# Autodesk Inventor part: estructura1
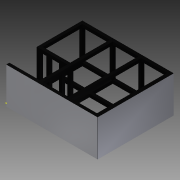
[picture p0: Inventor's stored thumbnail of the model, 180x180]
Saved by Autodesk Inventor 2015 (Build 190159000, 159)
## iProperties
Created: 2016-03
Part Number: estructura1
Material: Plástico, transparente
Document SubType Name: Modeling
Designer: Diego
Density: 1.188 g/cm^3
Appearance: Suave - Negro
Author: Diego
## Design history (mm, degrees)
sketch "Boceto1"
  geometry: L1 (0, 0)-(600, 0); L2 (600, 0)-(600, 500); L3 (600, 500)-(0, 500); L4 (0, 500)-(0, 300); L5 (0, 300)-(0, 200); L6 (0, 200)-(200, 200); L7 (200, 200)-(200, 20); L8 (200, 20)-(0, 20); L9 (0, 20)-(0, 0); L10 (220, 20)-(220, 220); L11 (200, 220)-(20, 220); L12 (20, 220)-(20, 480); L13 (576, 480)-(576, 20); L14 (200, 220)-(200, 480); L15 (220, 220)-(220, 480); L16 (408, 20)-(408, 480); L17 (388, 480)-(388, 20); L18 (20, 480)-(200, 480); L19 (220, 20)-(388, 20); L20 (408, 20)-(576, 20); L21 (220, 480)-(388, 480); L22 (408, 480)-(576, 480)
  constraints: 44 end point, 16 perpendicular, 2 parallel, 2 vertical, 1 horizontal, 1 point on line
extrude "Extrusión1" new body sketch "Boceto1" distance "d17" = 20; taper "d18" = 0 deg
node "Plano de trabajo1"
sketch "Boceto2"
  geometry: L1 (-388, 480)-(-220, 480) reference; L2 (-220, 480)-(-220, 20) reference; L3 (-220, 20)-(-388, 20) reference; L4 (-388, 20)-(-388, 480) reference; L5 (-408, 20)-(-576, 20) reference; L6 (-576, 20)-(-576, 480) reference; L7 (-576, 480)-(-408, 480) reference; L8 (-408, 480)-(-408, 20) reference; L9 (-20, 480)-(-20, 220) reference; L10 (-20, 220)-(-200, 220) reference; L11 (-200, 220)-(-200, 480) reference; L12 (-200, 480)-(-20, 480) reference; L13 (0, 0)-(-600, 0) reference; L14 (0, 20)-(0, 0) reference; L15 (-200, 20)-(0, 20) reference; L16 (-200, 200)-(-200, 20) reference; L17 (0, 200)-(-200, 200) reference; L18 (0, 500)-(0, 200) reference; L19 (-600, 500)-(0, 500) reference; L20 (-600, 0)-(-600, 500) reference; L21 (-220, 20)-(-220, 480) reference; L22 (-20, 220)-(-20, 480) reference; L23 (-576, 346)-(-408, 346); L24 (-576, 326)-(-408, 326); L25 (-388, 346)-(-220, 346); L26 (-200, 346)-(-20, 346); L27 (-388, 326)-(-220, 326); L28 (-200, 326)-(-20, 326); L29 (-220, 181)-(-388, 181); L30 (-408, 181)-(-576, 181); L31 (-220, 161)-(-388, 161); L32 (-408, 161)-(-576, 161); L33 (0, 200)-(0, 500); L34 (0, 500)-(-600, 500); L35 (-600, 500)-(-600, 0); L36 (-600, 0)-(0, 0); L37 (0, 20)-(0, 0); L38 (0, 20)-(-200, 20); L39 (-200, 20)-(-200, 200); L40 (0, 200)-(-200, 200); L41 (-220, 20)-(-580, 20); L42 (-580, 20)-(-580, 480); L43 (-580, 480)-(-20, 480); L44 (-20, 480)-(-20, 220); L45 (-20, 220)-(-220, 220); L46 (-220, 220)-(-220, 20); L47 (-200, 480)-(-200, 220); L48 (-388, 480)-(-388, 20); L49 (-408, 480)-(-408, 20); L50 (-20, 480)-(-200, 480); L51 (-200, 480)-(-200, 346); L52 (-200, 346)-(-20, 346); L53 (-20, 346)-(-20, 480); L54 (-20, 326)-(-200, 326); L55 (-200, 326)-(-200, 346); L56 (-200, 346)-(-20, 346); L57 (-20, 346)-(-20, 326); L58 (-220, 346)-(-388, 346); L59 (-388, 346)-(-388, 326); L60 (-388, 326)-(-220, 326); L61 (-220, 326)-(-220, 346); L62 (-220, 181)-(-388, 181); L63 (-388, 181)-(-388, 161); L64 (-388, 161)-(-220, 161)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; 1 further point
  constraints: 94 end point, 26 parallel, 18 point on line, 12 perpendicular, 5 horizontal, 4 collinear, 1 vertical, 5 other
  dimensions: "d22" = 20 distance between parallel lines of L36 L41; "d23" = 20 distance between parallel lines of L48 L49
extrude "Extrusión2" join sketch "Boceto2" distance "d24" = 20; taper "d25" = 0 deg
sketch "Boceto3"
  geometry: 1 further point
sketch "Boceto4"
  geometry: L1 (-220, 480)-(-220, 181) reference; L2 (-576, 181)-(-576, 480) reference; L3 (-220, 346)-(-576, 346); L4 (-576, 346)-(-576, 326); L5 (-576, 326)-(-220, 326); L6 (-220, 326)-(-220, 346); L7 (-388, 480)-(-388, 181) reference; L8 (-388, 346)-(-388, 326); L9 (-408, 181)-(-408, 480) reference; L10 (-408, 346)-(-408, 326); 1 further point
  constraints: 12 end point, 10 point on line, 2 parallel, 1 horizontal, 1 perpendicular
  dimensions: "d26" = 20 distance of L4.end L3.end
extrude "Extrusión3" join sketch "Boceto4" distance "d27" = 20; taper "d28" = 0 deg
sketch "Boceto5"
  geometry: L1 (0, 20)-(-20, 20); L2 (-20, 20)-(-20, 0); L3 (-20, 0)-(0, 0); L4 (0, 0)-(0, 20); L5 (-20, 220)-(0, 220); L6 (0, 220)-(0, 200); L7 (0, 200)-(-20, 200); L8 (-20, 200)-(-20, 220); L9 (-20, 480)-(0, 480); L10 (0, 480)-(0, 500); L11 (0, 500)-(-20, 500); L12 (-20, 500)-(-20, 480); L13 (-600, 500)-(-580, 500); L14 (-580, 500)-(-580, 480); L15 (-580, 480)-(-600, 480); L16 (-600, 480)-(-600, 500); 1 further point
  constraints: 32 end point, 8 parallel, 4 horizontal, 4 perpendicular, 2 point on line
  dimensions: "d29" = 20 distance of L3.end L2.end; "d30" = 20 distance of L2.end L1.end
extrude "Extrusión4" join sketch "Boceto5" distance "d31" = 200; taper "d32" = 0 deg
sketch "Boceto6"
  geometry: L1 (0, 500)-(-20, 500); L2 (-20, 500)-(-20, 480); L3 (-20, 480)-(0, 480); L4 (0, 480)-(0, 500); L5 (-20, 220)-(0, 220); L6 (0, 220)-(0, 200); L7 (0, 200)-(-20, 200); L8 (-20, 200)-(-20, 220); L9 (0, 500)-(-600, 500) reference; L10 (-200, 480)-(-220, 480); L11 (-220, 480)-(-220, 500); L12 (-220, 500)-(-200, 500); L13 (-200, 500)-(-200, 480); L14 (-388, 480)-(-408, 480); L15 (-408, 480)-(-408, 500); L16 (-408, 500)-(-388, 500); L17 (-388, 500)-(-388, 480); L18 (-600, 500)-(-580, 500); L19 (-580, 500)-(-580, 480); L20 (-580, 480)-(-600, 480); L21 (-600, 480)-(-600, 500); L22 (-200, 220)-(-220, 220); L23 (-220, 220)-(-220, 200); L24 (-220, 200)-(-200, 200); L25 (-200, 200)-(-200, 220); L26 (-200, 20)-(-220, 20); L27 (-220, 20)-(-220, 0); L28 (-220, 0)-(-200, 0); L29 (-200, 0)-(-200, 20); L30 (-600, 0)-(-20, 0) reference; L31 (-388, 20)-(-408, 20); L32 (-408, 20)-(-408, 0); L33 (-408, 0)-(-388, 0); L34 (-388, 0)-(-388, 20); L35 (-600, 0)-(-580, 0); L36 (-580, 0)-(-580, 20); L37 (-580, 20)-(-600, 20); L38 (-600, 20)-(-600, 0); 1 further point
  constraints: 72 end point, 18 parallel, 11 point on line, 9 horizontal, 9 perpendicular
extrude "Extrusión5" join sketch "Boceto6" distance "d33" = 200; taper "d34" = 0 deg
sketch "Boceto7"
  geometry: L1 (-601, 326)-(-581, 326); L2 (-581, 326)-(-581, 346); L3 (-581, 346)-(-601, 346); L4 (-601, 346)-(-601, 326); L5 (-601, 161)-(-581, 161); L6 (-581, 161)-(-581, 181); L7 (-581, 181)-(-601, 181); L8 (-601, 181)-(-601, 161); 1 further point
  constraints: 16 end point, 4 parallel, 2 horizontal, 2 perpendicular, 1 point on line
  dimensions: "d35" = 20 distance of L3.end L2.end; "d36" = 20 distance of L2.end L1.end; "d37" = 20 distance of L7.end L6.end; "d38" = 20 distance of L6.end L5.end
extrude "Extrusión6" join sketch "Boceto7" distance "d39" = 200; taper "d40" = 0 deg
sketch "Boceto8"
  geometry: L1 (-20, 0)-(220, 0) reference; L2 (0, 20)-(200, 20) reference; L3 (90, 0)-(110, 0); L4 (110, 0)-(110, 20); L5 (110, 20)-(90, 20); L6 (90, 20)-(90, 0); 1 further point
  constraints: 8 end point, 2 parallel, 2 point on line, 1 horizontal, 1 perpendicular
extrude "Extrusión7" join sketch "Boceto8" distance "d43" = 200; taper "d44" = 0 deg
sketch "Boceto9"
  geometry: L1 (220, 20)-(388, 20) reference; L2 (388, 0)-(220, 0) reference; L3 (251, 20)-(271, 20); L4 (271, 20)-(271, 0); L5 (271, 0)-(251, 0); L6 (251, 0)-(251, 20); L7 (271, 20)-(326, 20); L8 (326, 20)-(346, 20); L9 (346, 20)-(346, 0); L10 (346, 0)-(326, 0); L11 (326, 0)-(326, 20); 1 further point
  constraints: 18 end point, 4 parallel, 3 point on line, 2 horizontal, 2 perpendicular
  dimensions: "d46" = 20 distance of L9.end L10.end; "d47" = 20 distance of L8.end L9.end
extrude "Extrusión8" join sketch "Boceto9" distance "d48" = 220; taper "d49" = 0 deg
sketch "Boceto10"
  geometry: L1 (-200, 220)-(-20, 220) reference; L2 (-20, 200)-(-200, 200) reference; L3 (-63.349, 220)-(-83.349, 220); L4 (-83.349, 220)-(-83.349, 200); L5 (-83.349, 200)-(-63.349, 200); L6 (-63.349, 200)-(-63.349, 220); L7 (-166.733, 220)-(-146.733, 220); L8 (-146.733, 220)-(-146.733, 200); L9 (-146.733, 200)-(-166.733, 200); L10 (-166.733, 200)-(-166.733, 220); 1 further point
  constraints: 16 end point, 4 parallel, 4 point on line, 2 horizontal, 2 perpendicular
  dimensions: "d50" = 20 distance of L5.end L4.end; "d51" = 20 distance of L8.end L9.end
extrude "Extrusión9" join sketch "Boceto10" distance "d52" = 200; taper "d53" = 0 deg
sketch "Boceto11"
  geometry: L1 (239.914, 0)-(0, 0); L2 (0, 0)-(0, -1); L3 (0, -1)-(239.914, -1); L4 (239.914, -1)-(239.914, 0); 1 further point
  constraints: 8 end point, 2 parallel, 1 horizontal, 1 perpendicular
  dimensions: "d54" = 1 distance of L2.end L1.end
extrude "Extrusión10" join sketch "Boceto11" distance "d55" = 600; taper "d56" = 0 deg
sketch "Boceto12"
  geometry: L1 (601.172, 239.831)-(600.172, 239.831); L2 (600.172, 239.831)-(600.172, 0); L3 (600.172, 0)-(601.172, 0); L4 (601.172, 0)-(601.172, 239.831); 1 further point
  constraints: 8 end point, 2 parallel, 1 horizontal, 1 perpendicular
  dimensions: "d57" = 1 distance of L3.end L2.end
extrude "Extrusión11" join sketch "Boceto12" distance "d58" = 500; taper "d59" = 0 deg
node "Sólido1"
node "Contorno proyectado1"
